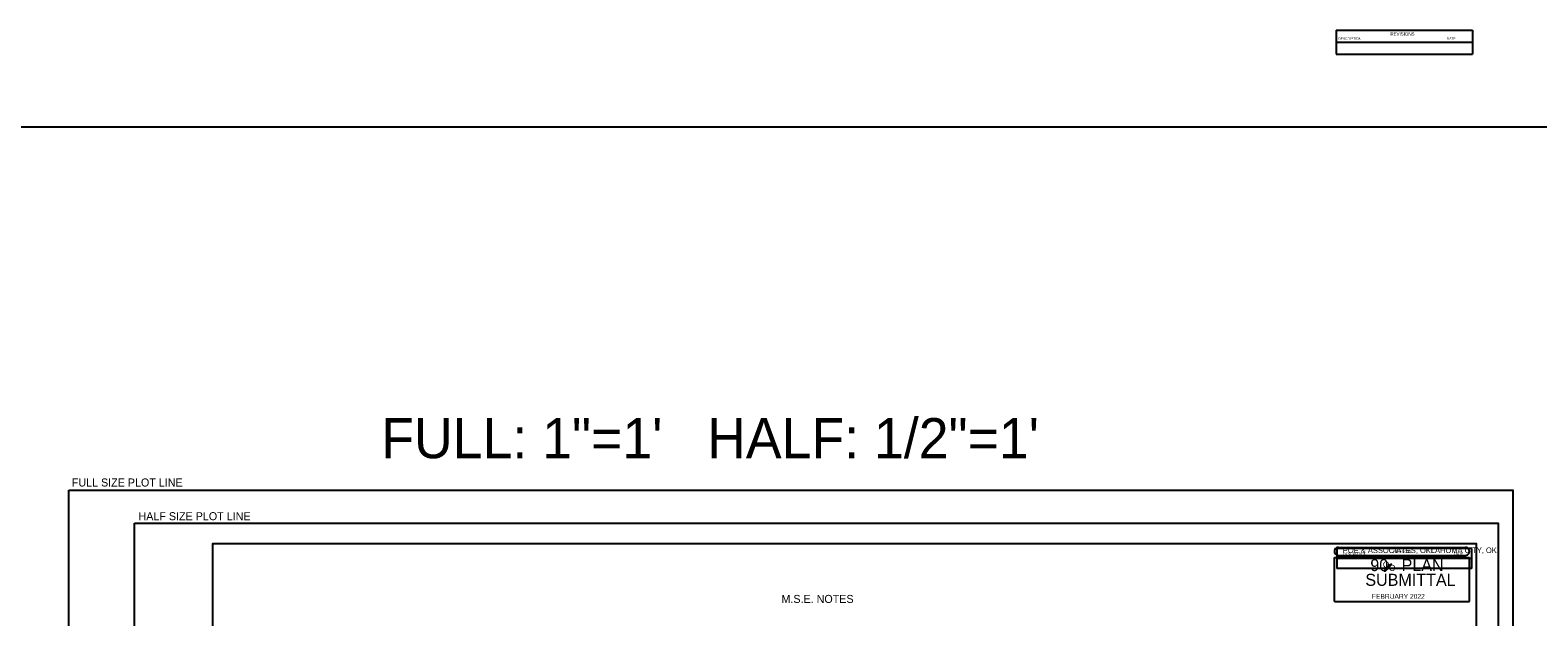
# Model space of a CAD drawing. Extents: x 2145640 to 2151866, y 143172 to 145639.
# Drawn here: x 2150645.64 to 2150683.23, y 144360.73 to 144375.34 of the extents above; entities that cross this region are included whole.
import ezdxf

# ---------------------------------------------------------------- set-up
doc = ezdxf.new("R2010")
doc.units = 0
for name, color, linetype in [('2', 7, 'Continuous'), ('4', 7, 'Continuous'), ('REVBLK', 7, 'Continuous'), ('S', 7, 'Continuous'), ('SHT_Date_Stamp', 7, 'Continuous'), ('SHT_Plot_Shape_Full', 7, 'Continuous'), ('SHT_Plot_Shape_Half', 7, 'Continuous'), ('SHT_Sheet_Border', 7, 'Continuous'), ('SHT_Stamp_90_Submit', 7, 'Continuous'), ('SHT_Stamp_Rev_Block', 7, 'Continuous')]:
    doc.layers.add(name, color=color, linetype=linetype)

msp = doc.modelspace()

# ---------------------------------------------------------------- linework, layer by layer
at = {"layer": '2'}
msp.add_lwpolyline([(2150627.287, 144372.931), (2150708.355, 144372.931), (2150708.355, 144332.003), (2150627.287, 144332.003)], close=True, dxfattribs=at)
at = {"layer": 'REVBLK'}
for p, q in [((2150678.206, 144375.342), (2150681.606, 144375.342)), ((2150678.206, 144375.342), (2150678.206, 144374.742)), ((2150678.206, 144375.042), (2150681.606, 144375.042)), ((2150681.606, 144375.342), (2150681.606, 144374.742)), ((2150678.206, 144374.742), (2150681.606, 144374.742))]:
    msp.add_line(p, q, dxfattribs=at)
at = {"layer": 'SHT_Plot_Shape_Full'}
msp.add_lwpolyline([(2150646.606, 144363.882), (2150682.606, 144363.882), (2150682.606, 144339.882), (2150646.606, 144339.882)], close=True, dxfattribs=at)
at = {"layer": 'SHT_Plot_Shape_Half'}
msp.add_lwpolyline([(2150648.244, 144363.057), (2150682.244, 144363.057), (2150682.244, 144341.057), (2150648.244, 144341.057)], close=True, dxfattribs=at)
at = {"layer": 'SHT_Sheet_Border'}
msp.add_lwpolyline([(2150681.694, 144341.557), (2150650.194, 144341.557), (2150650.194, 144362.557), (2150681.694, 144362.557)], close=True, dxfattribs=at)
at = {"layer": 'SHT_Stamp_90_Submit'}
for p, q in [((2150678.261, 144362.457), (2150681.427, 144362.457)), ((2150678.261, 144362.257), (2150681.427, 144362.257)), ((2150678.161, 144362.207), (2150681.527, 144362.207)), ((2150678.161, 144361.107), (2150678.161, 144362.207)), ((2150679.404, 144361.868), (2150679.56, 144362.041)), ((2150679.404, 144361.868), (2150679.435, 144361.868)), ((2150679.422, 144361.868), (2150679.578, 144362.041)), ((2150679.427, 144361.868), (2150679.583, 144362.041)), ((2150679.435, 144361.868), (2150679.59, 144362.041)), ((2150679.56, 144362.041), (2150679.59, 144362.041)), ((2150681.527, 144361.107), (2150681.527, 144362.207)), ((2150678.161, 144361.107), (2150681.527, 144361.107))]:
    msp.add_line(p, q, dxfattribs=at)
for centre, start, end in [((2150678.261, 144362.357), 89.9952, 270), ((2150681.427, 144362.357), 270, 90.0048)]:
    msp.add_arc(centre, 0.1, start, end, dxfattribs=at)
at = {"layer": 'SHT_Stamp_Rev_Block'}
for p, q in [((2150681.59, 144362.432), (2150678.225, 144362.432)), ((2150678.225, 144362.432), (2150678.225, 144361.932)), ((2150681.59, 144361.932), (2150681.59, 144362.432)), ((2150681.59, 144362.182), (2150678.225, 144362.182)), ((2150681.59, 144361.932), (2150678.225, 144361.932))]:
    msp.add_line(p, q, dxfattribs=at)

# ---------------------------------------------------------------- texts
at = {"layer": '4'}
msp.add_text('M.S.E. NOTES', height=0.2, dxfattribs=at).set_placement((2150664.374, 144361.072))
at = {"layer": 'Defpoints'}
for s, p in [('FULL SIZE PLOT LINE', (2150646.679, 144363.973)), ('HALF SIZE PLOT LINE', (2150648.342, 144363.133))]:
    msp.add_text(s, height=0.2, dxfattribs=at).set_placement(p)
at = {"layer": 'REVBLK'}
for s, height, p in [('DESCRIPTION', 0.06, (2150678.259, 144375.102)), ('REVISIONS', 0.08, (2150679.557, 144375.208)), ('DATE', 0.06, (2150680.963, 144375.102))]:
    msp.add_text(s, height=height, dxfattribs=at).set_placement(p)
at = {"layer": 'S'}
msp.add_text('FULL: 1"=1\'   HALF: 1/2"=1\'', height=1, dxfattribs=at).set_placement((2150654.394, 144364.677))
at = {"layer": 'SHT_Date_Stamp'}
msp.add_text('FEBRUARY 2022', height=0.12, dxfattribs=at).set_placement((2150679.097, 144361.176))
at = {"layer": 'SHT_Stamp_90_Submit'}
for s, height, p in [('POE & ASSOCIATES, OKLAHOMA CITY, OK.', 0.14, (2150678.371, 144362.314)), ('90   PLAN', 0.3, (2150679.056, 144361.865)), ('O', 0.153, (2150679.37, 144361.953)), ('O', 0.153, (2150679.522, 144361.869)), ('SUBMITTAL', 0.3, (2150678.932, 144361.498))]:
    msp.add_text(s, height=height, dxfattribs=at).set_placement(p)
at = {"layer": 'SHT_Stamp_Rev_Block'}
for s, p in [('DESCRIPTION', (2150678.384, 144362.261)), ('REVISIONS', (2150679.633, 144362.32)), ('DATE', (2150681.154, 144362.265))]:
    msp.add_text(s, height=0.06, dxfattribs=at).set_placement(p)

doc.saveas('drawing.dxf')
